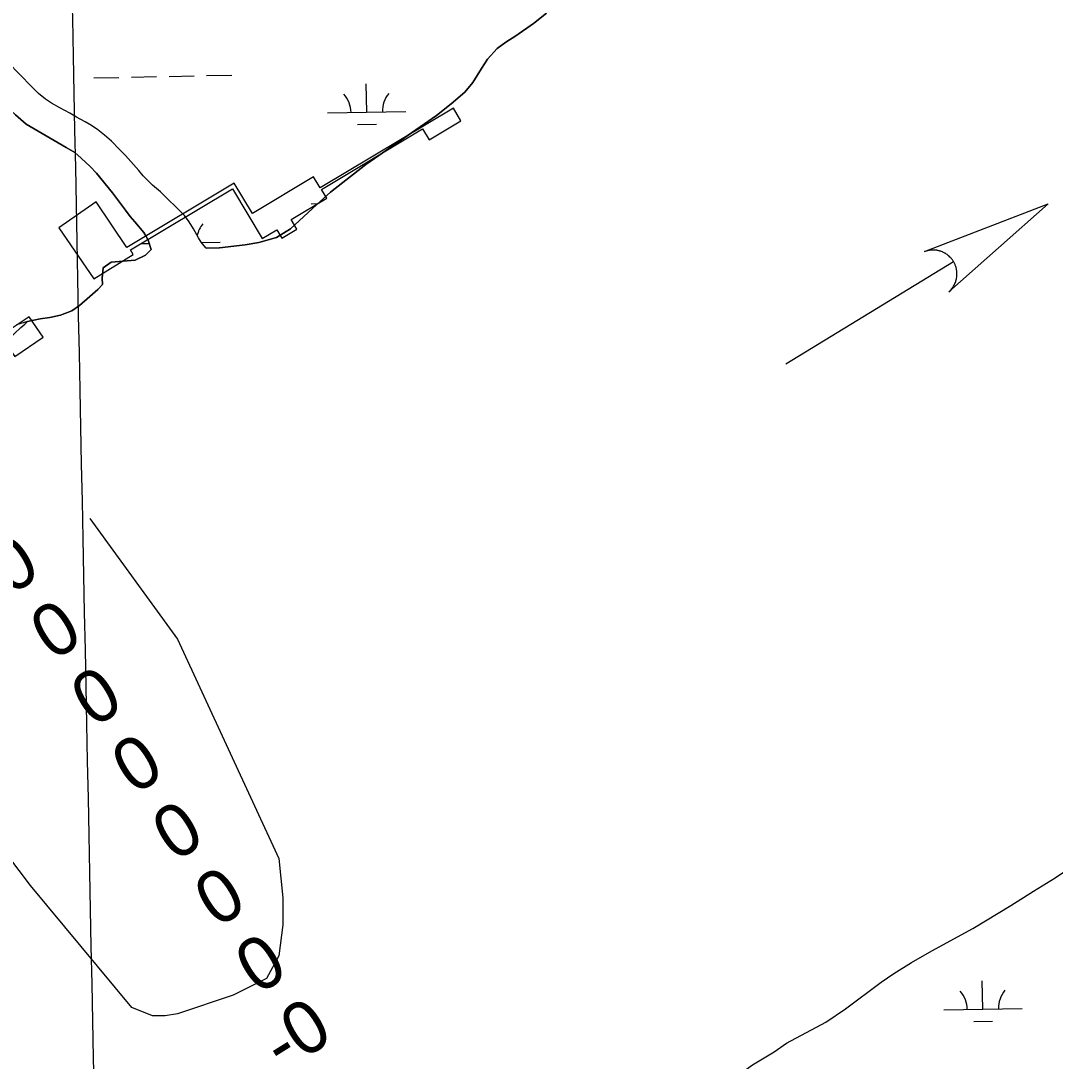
# Model space of a CAD drawing. Extents: x 3989314 to 4027622, y 243956 to 270014.
# Drawn here: x 4014522 to 4015842, y 263542 to 264869 of the extents above; entities that cross this region are included whole.
import ezdxf

# ---------------------------------------------------------------- set-up
doc = ezdxf.new("R2010")
doc.units = 0
for name, color, linetype in [('V-CHAN-DOCK', 7, 'Continuous'), ('V-GRID-MAJR', 7, 'Continuous'), ('V-RIVR-EDGE', 7, 'Continuous'), ('V-RIVR-RANG', 7, 'Continuous'), ('V-STRM-FLOW', 7, 'Continuous'), ('V-TOPO-SHOR', 7, 'Continuous'), ('V-TOPO-WATR', 7, 'Continuous'), ('V-WETL-SWMP', 7, 'Continuous')]:
    doc.layers.add(name, color=color, linetype=linetype)

msp = doc.modelspace()

# ---------------------------------------------------------------- linework, layer by layer
at = {"layer": 'V-CHAN-DOCK'}
for points in [[(4014793.98, 264661.804), (4014656.858, 264579.89400000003), (4014617.6550000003, 264638.022), (4014569.967, 264605.05), (4014614.909, 264539.729), (4014665.015, 264570.952), (4014661.488, 264576.855), (4014791.5810000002, 264654.564), (4014829.443, 264591.185), (4014848.166, 264602.369), (4014854.5470000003, 264591.684), (4014873.864, 264603.223), (4014866.542, 264615.476), (4014911.914, 264642.577), (4014905.116, 264653.956), (4015034.269, 264731.104), (4015042.701, 264716.989), (4015083.3310000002, 264741.26), (4015073.642, 264757.632), (4014903.447, 264655.93), (4014895.194, 264669.82), (4014817.069, 264623.152), (4014793.98, 264661.804)], [(4014482.591, 264467.424), (4014499.895, 264441.844), (4014508.9250000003, 264447.954), (4014513.754, 264440.814), (4014549.899, 264465.265), (4014532.231, 264491.384), (4014495.35, 264466.435), (4014505.9590000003, 264450.751), (4014500.393, 264446.987), (4014485.319, 264469.26900000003), (4014482.591, 264467.424)]]:
    msp.add_lwpolyline(points, dxfattribs=at)
at = {"layer": 'V-GRID-MAJR'}
msp.add_spline([(4014889.957, 249819.943), (4014768.3740000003, 255876.52300000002), (4014646.73, 261936.18600000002), (4014525.085, 267995.84), (4014525.023, 267998.933)], degree=3, dxfattribs=at)
at = {"layer": 'V-RIVR-EDGE'}
for points in [[(4014758.041, 264578.942), (4014775.0870000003, 264579.185), (4014807.73, 264583.208), (4014825.273, 264586.061), (4014847.926, 264592.506), (4014865.664, 264603.438), (4014899.394, 264634.518), (4014916.81, 264650.263), (4014961.791, 264685.878), (4015031.308, 264733.572), (4015052.196, 264748.36), (4015070.9020000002, 264763.2), (4015088.079, 264778.077), (4015098.6380000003, 264790.275), (4015109.56, 264808.36100000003), (4015117.045, 264819.975), (4015129.395, 264833.877), (4015140.7290000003, 264841.905), (4015153.365, 264849.681), (4015176.026, 264865.518), (4015192.289, 264878.67100000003)], [(4014505.2830000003, 264462.365), (4014521.6610000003, 264477.816), (4014526.605, 264482.143), (4014530.148, 264485.254), (4014546.3910000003, 264488.578), (4014558.664, 264490.24700000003), (4014572.0640000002, 264493.419), (4014586.609, 264498.748), (4014596.612, 264505.93700000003), (4014609.77, 264517.197), (4014619.8140000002, 264526.13), (4014625.648, 264532.54), (4014625.407, 264540.63), (4014626.595, 264553.706), (4014636.949, 264561.173), (4014667.507, 264563.678), (4014680.809, 264569.838), (4014688.1180000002, 264577.027)], [(4015301.6890000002, 263432.50800000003), (4015388.84, 263486.77), (4015415.296, 263506.011), (4015438.457, 263524.455), (4015455.14, 263536.944), (4015482.843, 263553.533), (4015498.8340000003, 263564.506), (4015548.848, 263591.48), (4015574.159, 263608.567), (4015619.535, 263642.422), (4015635.525, 263653.397), (4015658.145, 263667.487), (4015684.278, 263682.368), (4015736.512, 263710.819), (4015785.058, 263740.232), (4015814.1070000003, 263758.318), (4015841.3880000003, 263775.575), (4015862.923, 263789.909)]]:
    msp.add_lwpolyline(points, dxfattribs=at)
at = {"layer": 'V-STRM-FLOW'}
msp.add_line((4015498.031813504, 264431.5080763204), (4015711.808090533, 264561.8894023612), dxfattribs=at)
msp.add_lwpolyline([(4015674.843791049, 264574.48445026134), (4015832.6978689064, 264635.6190202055), (4015706.08581938, 264523.2603074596), (4015708.251833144, 264525.3965160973), (4015710.1295241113, 264527.6555969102), (4015710.8220506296, 264528.6151267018), (4015711.4036924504, 264529.48029283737), (4015712.065182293, 264530.55929088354), (4015712.6635781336, 264531.62146246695), (4015713.1450684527, 264532.5619254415), (4015713.7514376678, 264533.8742333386), (4015714.3328269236, 264535.31491542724), (4015714.6256088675, 264536.13309615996), (4015714.9686717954, 264537.1982416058), (4015715.3618003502, 264538.620985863), (4015715.6184201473, 264539.7399787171), (4015715.8462253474, 264540.951327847), (4015715.9704757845, 264541.75746627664), (4015716.0837235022, 264542.64384754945), (4015716.1835669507, 264543.72977873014), (4015716.243002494, 264544.73449926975), (4015716.267083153, 264545.73676475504), (4015716.2633176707, 264546.5567544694), (4015716.21864112, 264547.77690119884), (4015716.127428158, 264548.9438093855), (4015716.02300933, 264549.874020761), (4015715.8636134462, 264550.9637859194), (4015715.693878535, 264551.9042828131), (4015715.5200225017, 264552.73305251), (4015715.3656274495, 264553.3711782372), (4015715.106671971, 264554.3436071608), (4015714.8099424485, 264555.3304968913), (4015714.49597468, 264556.25769719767), (4015714.145988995, 264557.1887321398), (4015713.7948567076, 264558.04015138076), (4015713.3826371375, 264558.9582662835), (4015713.0219541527, 264559.70120171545), (4015712.470214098, 264560.7483355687), (4015711.808090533, 264561.8894023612), (4015711.586337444, 264562.249509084), (4015711.251906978, 264562.76753875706), (4015710.8411577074, 264563.37609679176), (4015710.430247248, 264563.95601969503), (4015710.017222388, 264564.5077375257), (4015709.6038033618, 264565.0390631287), (4015709.1001959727, 264565.65373138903), (4015708.7399260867, 264566.07300741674), (4015708.199243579, 264566.6774077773), (4015707.6771077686, 264567.2265269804), (4015707.3108529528, 264567.60001903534), (4015706.3393702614, 264568.52659022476), (4015705.802182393, 264569.00734704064), (4015705.4262692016, 264569.3276723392), (4015704.7952913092, 264569.847510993), (4015704.221727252, 264570.29327119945), (4015703.6106221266, 264570.7452493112), (4015702.874439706, 264571.2616292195), (4015702.170906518, 264571.7216707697), (4015701.614670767, 264572.06941215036), (4015701.132961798, 264572.35569035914), (4015700.468206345, 264572.7314214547), (4015699.866025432, 264573.0565126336), (4015699.1561849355, 264573.4134999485), (4015698.425325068, 264573.758732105), (4015697.6803985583, 264574.08658244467), (4015696.7212459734, 264574.47388857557), (4015696.0263505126, 264574.7313339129), (4015695.2531295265, 264574.9957854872), (4015694.48689716, 264575.23617138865), (4015693.8646111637, 264575.4141445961), (4015693.183101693, 264575.59287024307), (4015692.16262951, 264575.831893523), (4015692.12313523, 264575.83854148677), (4015691.5154895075, 264575.9620936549), (4015691.0628104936, 264576.0453814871), (4015690.380781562, 264576.1566407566), (4015689.5325684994, 264576.2758198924), (4015688.8549478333, 264576.35129422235), (4015688.242876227, 264576.40824013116), (4015687.4581337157, 264576.46224675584), (4015686.7012021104, 264576.49374675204), (4015686.1592849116, 264576.5065754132), (4015685.4527426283, 264576.5065016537), (4015684.47855692, 264576.481393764), (4015683.900496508, 264576.4509829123), (4015683.4471727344, 264576.4197302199), (4015683.032250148, 264576.3861660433), (4015682.5381778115, 264576.33726266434), (4015681.8886193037, 264576.26115724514), (4015681.241910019, 264576.1700891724), (4015680.6028164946, 264576.06710474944), (4015679.9693855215, 264575.95263403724), (4015679.1579617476, 264575.7831503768), (4015678.6724729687, 264575.67092001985), (4015677.900149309, 264575.4743961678), (4015677.011439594, 264575.2236300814), (4015676.353889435, 264575.01821856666), (4015675.86112555, 264574.85434460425), (4015675.4037165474, 264574.69292569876), (4015675.073785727, 264574.5710193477)], close=True, dxfattribs=at)
at = {"layer": 'V-TOPO-SHOR'}
for points in [[(4014758.041, 264578.9420000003), (4014755.444, 264581.86200000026), (4014751.557, 264586.72200000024), (4014748.252, 264591.94900000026), (4014741.858, 264603.53800000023), (4014736.359, 264612.62900000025), (4014730.2600000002, 264620.59200000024), (4014723.0100000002, 264628.20000000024), (4014706.245, 264644.42400000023), (4014699.722, 264650.6810000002), (4014689.642, 264659.50200000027), (4014677.7290000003, 264671.41500000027), (4014672.171, 264678.03000000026), (4014655.287, 264697.30800000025), (4014647.093, 264705.32000000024), (4014637.42, 264715.27500000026), (4014628.274, 264723.30900000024), (4014619.852, 264729.80100000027), (4014611.603, 264735.5280000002), (4014603.903, 264740.28700000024), (4014592.794, 264746.0830000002), (4014584.1520000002, 264751.2460000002), (4014571.1610000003, 264758.04100000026), (4014560.821, 264764.0070000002), (4014553.125, 264768.9570000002), (4014543.964, 264776.42200000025), (4014535.213, 264785.02000000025), (4014505.642, 264815.6580000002)], [(4014688.1180000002, 264577.02700000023), (4014684.213, 264588.94000000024), (4014681.663, 264593.9580000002), (4014678.73, 264598.79300000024), (4014667.239, 264612.41200000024), (4014660.927, 264619.42700000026), (4014655.213, 264627.56900000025), (4014638.401, 264649.70400000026), (4014618.0360000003, 264674.7840000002), (4014610.041, 264683.17300000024), (4014598.4820000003, 264693.93500000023), (4014590.451, 264700.8000000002), (4014579.3680000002, 264707.54600000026), (4014528.608, 264736.9800000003), (4014514.6040000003, 264749.13500000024), (4014503.045, 264759.89700000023), (4014477.971, 264786.07000000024)]]:
    msp.add_lwpolyline(points, dxfattribs=at)
at = {"layer": 'V-TOPO-WATR'}
msp.add_lwpolyline([(4014609.6624305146, 264234.18367450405), (4014721.4970509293, 264080.0239028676), (4014850.839343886, 263800.08326001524), (4014856.118621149, 263749.9052202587), (4014856.118621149, 263715.5728772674), (4014850.839343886, 263675.95863535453), (4014835.0015120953, 263646.9081912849), (4014792.767293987, 263625.780595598), (4014721.4970509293, 263602.0120504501), (4014705.6592191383, 263599.3711009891), (4014689.8213873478, 263599.3711009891), (4014663.42500103, 263609.9348988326), (4014534.0827080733, 263765.75091702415), (4014383.623306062, 263963.8221265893), (4014331.3760557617, 264065.8793187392)], dxfattribs=at)
at = {"layer": 'V-WETL-SWMP'}
for p, q in [((4014614.770397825, 264796.2091097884), (4014646.7640450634, 264796.8467118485)), ((4014662.760868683, 264797.16551287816), (4014694.754515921, 264797.80311493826)), ((4014710.7513395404, 264798.1219159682), (4014742.7449867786, 264798.759518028)), ((4014758.741810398, 264799.07831905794), (4014790.7354576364, 264799.7159211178)), ((4014963.0284849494, 264752.3974769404), (4014962.3111826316, 264788.3903300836)), ((4014913.0384111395, 264751.40122372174), (4015013.0185587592, 264753.39373015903)), ((4014951.338330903, 264736.7304395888), (4014975.333566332, 264737.2086411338)), ((4014891.935048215, 264635.52573381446), (4014900.7029640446, 264635.70046979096)), ((4014675.839261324, 264584.7799371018), (4014685.512893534, 264584.972723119)), ((4014751.8989095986, 264586.29573141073), (4014775.819408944, 264586.77244353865)), ((4015749.3317661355, 263607.95042045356), (4015748.614463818, 263643.94327359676)), ((4015699.3416923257, 263606.9541672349), (4015799.321839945, 263608.9466736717)), ((4015737.6416120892, 263592.2833831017), (4015761.6368475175, 263592.76158464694))]:
    msp.add_line(p, q, dxfattribs=at)
for points in [[(4015192.288, 264878.67100000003), (4015176.026, 264865.51900000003), (4015153.365, 264849.68200000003), (4015140.728, 264841.904), (4015129.394, 264833.876), (4015117.046, 264819.975)], [(4015117.046, 264819.975), (4015109.559, 264808.36), (4015098.639, 264790.27400000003), (4015088.079, 264778.077), (4015070.9020000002, 264763.2), (4015052.196, 264748.36), (4015031.308, 264733.572), (4014961.791, 264685.878), (4014916.811, 264650.263), (4014899.395, 264634.518), (4014865.664, 264603.438), (4014847.926, 264592.506), (4014825.273, 264586.061), (4014807.7290000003, 264583.207), (4014775.086, 264579.186), (4014758.042, 264578.941), (4014755.444, 264581.863), (4014751.558, 264586.722), (4014748.252, 264591.94800000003), (4014741.859, 264603.539), (4014736.36, 264612.63), (4014730.261, 264620.592), (4014723.0100000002, 264628.2), (4014706.245, 264644.425), (4014699.723, 264650.681), (4014689.642, 264659.501), (4014677.7290000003, 264671.416), (4014672.17, 264678.03), (4014655.288, 264697.30700000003), (4014647.093, 264705.32), (4014637.421, 264715.27400000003), (4014628.274, 264723.309), (4014619.852, 264729.802), (4014611.603, 264735.528), (4014603.9020000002, 264740.288), (4014592.795, 264746.083), (4014584.151, 264751.24700000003), (4014571.162, 264758.041), (4014560.821, 264764.00800000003), (4014553.125, 264768.958), (4014543.964, 264776.422), (4014535.2120000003, 264785.02), (4014505.6410000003, 264815.658)], [(4014514.6040000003, 264749.134), (4014528.608, 264736.979), (4014579.367, 264707.54600000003), (4014590.451, 264700.799), (4014598.4820000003, 264693.934), (4014610.041, 264683.172), (4014618.0360000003, 264674.783), (4014638.401, 264649.704), (4014655.214, 264627.569), (4014660.9280000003, 264619.426), (4014667.24, 264612.412), (4014678.73, 264598.792), (4014681.664, 264593.957), (4014684.2120000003, 264588.939), (4014688.119, 264577.027), (4014680.809, 264569.839), (4014667.508, 264563.678), (4014636.949, 264561.173), (4014626.594, 264553.707), (4014625.406, 264540.629), (4014625.648, 264532.541), (4014619.8140000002, 264526.129), (4014609.77, 264517.196), (4014596.612, 264505.936), (4014586.609, 264498.749), (4014572.065, 264493.42), (4014558.664, 264490.24700000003), (4014546.3910000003, 264488.577), (4014530.148, 264485.254), (4014516.066, 264481.006)], [(4015455.139, 263536.943), (4015482.842, 263553.533), (4015498.833, 263564.506), (4015548.848, 263591.481), (4015574.16, 263608.566), (4015619.535, 263642.423), (4015635.526, 263653.397), (4015658.145, 263667.488), (4015684.278, 263682.368), (4015736.5130000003, 263710.819), (4015785.057, 263740.232), (4015814.1070000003, 263758.318), (4015841.389, 263775.574), (4015862.9220000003, 263789.909)]]:
    msp.add_lwpolyline(points, dxfattribs=at)
for centre, radius, start, end in [((4014907.7870554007, 264751.77146680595), 35.24628790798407, 0.3698775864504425, 41.913535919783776), ((4015018.25099353, 264753.9729049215), 35.246287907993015, 140.36987458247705, 181.91353291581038), ((4014781.0518437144, 264587.35161830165), 35.246287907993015, 140.36987458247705, 167.6326057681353), ((4015694.090336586, 263607.32441031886), 35.24628790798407, 0.3698775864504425, 41.913535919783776), ((4015804.5542747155, 263609.5258484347), 35.246287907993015, 140.36987458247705, 181.91353291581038)]:
    msp.add_arc(centre, radius, start, end, dxfattribs=at)

# ---------------------------------------------------------------- texts
at = {"layer": 'V-RIVR-RANG'}
for s, p in [('0', (4014507.7615354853, 264135.23106923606)), ('0', (4014562.0615354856, 264051.20106923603)), ('0', (4014613.9615354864, 263966.10106923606)), ('0', (4014665.8815354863, 263880.40106923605)), ('0', (4014717.6115354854, 263794.80106923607)), ('0', (4014771.4415354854, 263710.60106923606)), ('0', (4014823.6915354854, 263625.35106923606)), ('-0', (4014855.6156387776, 263527.3626892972))]:
    msp.add_text(s, height=67, rotation=31.97488888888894, dxfattribs=at).set_placement(p)

doc.saveas('drawing.dxf')
